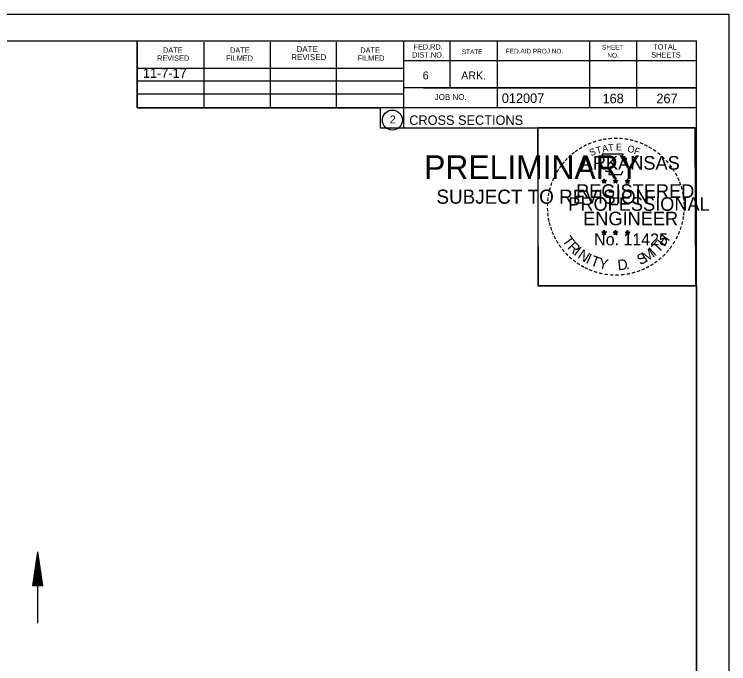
# Model space of a CAD drawing. Extents: x 1374311 to 1383814, y 384102 to 406278.
# Drawn here: x 1381686.5 to 1381791.6, y 388495.9 to 388591.4 of the extents above; entities that cross this region are included whole.
import ezdxf

# ---------------------------------------------------------------- set-up
doc = ezdxf.new("R2010")
doc.units = 0
for name, color, linetype in [('R_Border', 7, 'Continuous'), ('R_Border PE', 7, 'Continuous'), ('R_Border Prem', 7, 'Continuous'), ('R_Draft', 7, 'Continuous'), ('R_Fin Surface', 7, 'Continuous'), ('R_No Plot', 7, 'Continuous'), ('R_Water', 7, 'Continuous')]:
    doc.layers.add(name, color=color, linetype=linetype)

msp = doc.modelspace()

# ---------------------------------------------------------------- linework, layer by layer
at = {"layer": 'R_Border'}
for p, q in [((1381470.66, 388587.46), (1381786.84, 388587.46)), ((1381704.58, 388577.58), (1381704.58, 388587.46)), ((1381714.44, 388577.58), (1381714.44, 388587.26)), ((1381724.2, 388577.58), (1381724.2, 388587.26)), ((1381733.88, 388577.58), (1381733.88, 388587.26)), ((1381743.74, 388587.46), (1381743.74, 388574.66)), ((1381750.58, 388587.46), (1381750.58, 388580.52)), ((1381757.52, 388587.46), (1381757.52, 388577.58)), ((1381771.1, 388587.46), (1381771.1, 388577.58)), ((1381778.04, 388587.46), (1381778.04, 388577.58)), ((1381786.84, 388382), (1381786.84, 388587.46)), ((1381786.84, 388584.52), (1381743.74, 388584.52)), ((1381786.84, 388584.54), (1381786.84, 388584.54)), ((1381704.58, 388583.44), (1381743.74, 388583.44)), ((1381704.58, 388581.58), (1381743.74, 388581.58)), ((1381786.84, 388580.52), (1381743.74, 388580.52)), ((1381746.7, 388580.52), (1381786.84, 388580.52)), ((1381704.58, 388577.58), (1381704.58, 388579.64)), ((1381704.58, 388579.64), (1381743.74, 388579.64)), ((1381786.84, 388577.58), (1381704.58, 388577.58)), ((1381743.74, 388574.66), (1381786.84, 388574.66))]:
    msp.add_line(p, q, dxfattribs=at)
msp.add_circle((1381742.12, 388575.8), 1.47, dxfattribs=at)
at = {"layer": 'R_Border PE'}
for p, q in [((1381772.92, 388566.92), (1381773.27, 388566.81)), ((1381772.92, 388566.92), (1381773.18, 388566.87)), ((1381772.92, 388566.92), (1381773.16, 388566.8)), ((1381773.06, 388566.51), (1381773.27, 388566.81)), ((1381773.06, 388566.51), (1381773.18, 388566.76)), ((1381773.06, 388566.51), (1381773.27, 388566.73)), ((1381773.27, 388567.17), (1381773.23, 388566.92)), ((1381773.27, 388566.81), (1381773.27, 388567.17)), ((1381773.27, 388567.17), (1381773.32, 388566.92)), ((1381773.62, 388566.92), (1381773.27, 388566.81)), ((1381773.48, 388566.51), (1381773.27, 388566.81)), ((1381773.48, 388566.51), (1381773.27, 388566.73)), ((1381773.62, 388566.92), (1381773.33, 388566.87)), ((1381773.48, 388566.51), (1381773.35, 388566.8)), ((1381773.62, 388566.92), (1381773.41, 388566.82)), ((1381774.59, 388566.92), (1381774.94, 388566.81)), ((1381774.59, 388566.92), (1381774.85, 388566.87)), ((1381774.59, 388566.92), (1381774.83, 388566.8)), ((1381774.73, 388566.51), (1381774.94, 388566.81)), ((1381774.73, 388566.51), (1381774.85, 388566.76)), ((1381774.73, 388566.51), (1381774.94, 388566.73)), ((1381774.94, 388567.17), (1381774.9, 388566.92)), ((1381774.94, 388566.81), (1381774.94, 388567.17)), ((1381774.94, 388567.17), (1381774.99, 388566.92)), ((1381775.29, 388566.92), (1381774.94, 388566.81)), ((1381775.15, 388566.51), (1381774.94, 388566.81)), ((1381775.15, 388566.51), (1381774.94, 388566.73)), ((1381775.29, 388566.92), (1381775, 388566.87)), ((1381775.15, 388566.51), (1381775.02, 388566.8)), ((1381775.29, 388566.92), (1381775.08, 388566.82)), ((1381776.36, 388566.91), (1381776.71, 388566.8)), ((1381776.36, 388566.91), (1381776.61, 388566.86)), ((1381776.36, 388566.91), (1381776.59, 388566.79)), ((1381776.49, 388566.5), (1381776.71, 388566.8)), ((1381776.49, 388566.5), (1381776.62, 388566.74)), ((1381776.49, 388566.5), (1381776.7, 388566.72)), ((1381776.71, 388567.16), (1381776.66, 388566.91)), ((1381776.92, 388566.5), (1381776.7, 388566.71)), ((1381776.71, 388566.8), (1381776.71, 388567.16)), ((1381776.71, 388567.16), (1381776.75, 388566.91)), ((1381777.05, 388566.91), (1381776.71, 388566.8)), ((1381776.92, 388566.5), (1381776.71, 388566.8)), ((1381777.05, 388566.91), (1381776.77, 388566.86)), ((1381776.92, 388566.5), (1381776.78, 388566.79)), ((1381777.05, 388566.91), (1381776.85, 388566.81)), ((1381772.92, 388559.35), (1381773.27, 388559.24)), ((1381772.92, 388559.35), (1381773.17, 388559.3)), ((1381772.92, 388559.35), (1381773.16, 388559.22)), ((1381773.05, 388558.94), (1381773.27, 388559.24)), ((1381773.27, 388559.6), (1381773.23, 388559.35)), ((1381773.27, 388559.24), (1381773.27, 388559.6)), ((1381773.27, 388559.6), (1381773.32, 388559.35)), ((1381773.61, 388559.35), (1381773.27, 388559.24)), ((1381773.48, 388558.94), (1381773.27, 388559.24)), ((1381773.61, 388559.35), (1381773.33, 388559.3)), ((1381773.48, 388558.94), (1381773.34, 388559.23)), ((1381773.61, 388559.35), (1381773.41, 388559.24)), ((1381774.59, 388559.35), (1381774.94, 388559.24)), ((1381774.59, 388559.35), (1381774.84, 388559.3)), ((1381774.59, 388559.35), (1381774.82, 388559.22)), ((1381774.72, 388558.94), (1381774.94, 388559.24)), ((1381774.94, 388559.6), (1381774.9, 388559.35)), ((1381774.94, 388559.24), (1381774.94, 388559.6)), ((1381774.94, 388559.6), (1381774.99, 388559.35)), ((1381775.28, 388559.35), (1381774.94, 388559.24)), ((1381775.15, 388558.94), (1381774.94, 388559.24)), ((1381775.28, 388559.35), (1381775, 388559.3)), ((1381775.15, 388558.94), (1381775.01, 388559.23)), ((1381775.28, 388559.35), (1381775.08, 388559.24)), ((1381776.35, 388559.34), (1381776.7, 388559.23)), ((1381776.35, 388559.34), (1381776.61, 388559.29)), ((1381776.35, 388559.34), (1381776.59, 388559.21)), ((1381776.49, 388558.93), (1381776.7, 388559.23)), ((1381776.7, 388559.59), (1381776.66, 388559.34)), ((1381776.7, 388559.23), (1381776.7, 388559.59)), ((1381776.7, 388559.59), (1381776.75, 388559.34)), ((1381777.05, 388559.34), (1381776.7, 388559.23)), ((1381776.92, 388558.93), (1381776.7, 388559.23)), ((1381777.05, 388559.34), (1381776.76, 388559.29)), ((1381777.05, 388559.34), (1381776.85, 388559.23)), ((1381773.05, 388558.94), (1381773.18, 388559.18)), ((1381773.05, 388558.94), (1381773.27, 388559.16)), ((1381773.48, 388558.94), (1381773.27, 388559.15)), ((1381774.72, 388558.94), (1381774.85, 388559.18)), ((1381774.72, 388558.94), (1381774.93, 388559.16)), ((1381775.15, 388558.94), (1381774.93, 388559.15)), ((1381776.49, 388558.93), (1381776.61, 388559.17)), ((1381776.49, 388558.93), (1381776.7, 388559.15)), ((1381776.92, 388558.93), (1381776.7, 388559.14)), ((1381776.92, 388558.93), (1381776.78, 388559.22))]:
    msp.add_line(p, q, dxfattribs=at)
for points in [[(1381772.96, 388570.8), (1381773.23, 388569.97)], [(1381776.47, 388569.88), (1381776.62, 388570.16), (1381775.93, 388570.14), (1381776.08, 388570.8), (1381772.96, 388570.8)], [(1381773.46, 388568.37), (1381773.46, 388568.29), (1381774.02, 388568.27), (1381773.96, 388567.8), (1381775.83, 388567.8), (1381776.04, 388568.33)], [(1381773.27, 388567.17), (1381773.48, 388566.51), (1381772.92, 388566.92), (1381773.62, 388566.92), (1381773.06, 388566.51), (1381773.27, 388567.17)], [(1381774.94, 388567.17), (1381775.15, 388566.51), (1381774.59, 388566.92), (1381775.29, 388566.92), (1381774.73, 388566.51), (1381774.94, 388567.17)], [(1381776.71, 388567.16), (1381776.92, 388566.5), (1381776.36, 388566.91), (1381777.05, 388566.91), (1381776.49, 388566.5), (1381776.71, 388567.16)], [(1381773.27, 388559.6), (1381773.48, 388558.94), (1381772.92, 388559.35), (1381773.61, 388559.35), (1381773.05, 388558.94), (1381773.27, 388559.6)], [(1381774.94, 388559.6), (1381775.15, 388558.94), (1381774.59, 388559.35), (1381775.28, 388559.35), (1381774.72, 388558.94), (1381774.94, 388559.6)], [(1381776.7, 388559.59), (1381776.92, 388558.93), (1381776.35, 388559.34), (1381777.05, 388559.34), (1381776.49, 388558.93), (1381776.7, 388559.59)]]:
    msp.add_lwpolyline(points, dxfattribs=at)
for centre, radius in [((1381773.27, 388566.81), 0.172), ((1381773.27, 388566.81), 0.145), ((1381773.27, 388566.81), 0.116), ((1381773.27, 388566.81), 0.0991), ((1381773.27, 388566.81), 0.0747), ((1381773.27, 388566.81), 0.0495), ((1381773.27, 388566.81), 0.0296), ((1381774.94, 388566.81), 0.172), ((1381774.94, 388566.81), 0.145), ((1381774.94, 388566.81), 0.116), ((1381774.94, 388566.81), 0.0991), ((1381774.94, 388566.81), 0.0747), ((1381774.94, 388566.81), 0.0495), ((1381774.94, 388566.81), 0.0296), ((1381776.7, 388566.8), 0.172), ((1381776.7, 388566.8), 0.145), ((1381776.7, 388566.8), 0.116), ((1381776.7, 388566.8), 0.0991), ((1381776.7, 388566.8), 0.0747), ((1381776.7, 388566.8), 0.0495), ((1381776.7, 388566.8), 0.0296), ((1381773.27, 388559.23), 0.172), ((1381773.27, 388559.23), 0.145), ((1381773.27, 388559.23), 0.116), ((1381773.27, 388559.23), 0.0991), ((1381773.27, 388559.23), 0.0747), ((1381773.27, 388559.23), 0.0495), ((1381773.27, 388559.23), 0.0296), ((1381774.94, 388559.23), 0.172), ((1381774.94, 388559.23), 0.145), ((1381774.94, 388559.23), 0.116), ((1381774.94, 388559.23), 0.0991), ((1381774.94, 388559.23), 0.0747), ((1381774.94, 388559.23), 0.0495), ((1381774.94, 388559.23), 0.0296), ((1381776.7, 388559.22), 0.172), ((1381776.7, 388559.22), 0.145), ((1381776.7, 388559.22), 0.116), ((1381776.7, 388559.22), 0.0991), ((1381776.7, 388559.22), 0.0747), ((1381776.7, 388559.22), 0.0495), ((1381776.7, 388559.22), 0.0296)]:
    msp.add_circle(centre, radius, dxfattribs=at)
at = {"layer": 'R_Draft'}
for p, q in [((1381689.21, 388507.32), (1381689.96, 388512.32)), ((1381690.71, 388507.32), (1381689.96, 388512.32)), ((1381689.34, 388507.32), (1381689.96, 388511.49)), ((1381690.59, 388507.32), (1381689.96, 388511.49)), ((1381689.47, 388507.32), (1381689.96, 388510.63)), ((1381690.46, 388507.32), (1381689.96, 388510.63)), ((1381689.59, 388507.32), (1381689.96, 388509.79)), ((1381689.72, 388507.32), (1381689.96, 388508.95)), ((1381690.34, 388507.32), (1381689.96, 388509.79)), ((1381690.21, 388507.32), (1381689.96, 388508.95)), ((1381689.85, 388507.32), (1381689.96, 388508.11)), ((1381690.08, 388507.32), (1381689.96, 388508.11)), ((1381690.71, 388507.32), (1381689.21, 388507.32))]:
    msp.add_line(p, q, dxfattribs=at)
at = {"layer": 'R_No Plot'}
for p, q in [((1381458.26, 388591.36), (1381791.59, 388591.36)), ((1381762.87, 388552.21), (1381762.87, 388552.21))]:
    msp.add_line(p, q, dxfattribs=at)
for points in [[(1381458.25, 388591.36), (1381791.59, 388591.36), (1381791.59, 388378.02), (1381458.25, 388378.02)], [(1381704.58, 388587.46), (1381704.58, 388577.58), (1381740.31, 388577.58), (1381740.31, 388574.66), (1381763.51, 388574.66), (1381763.51, 388551.45), (1381786.84, 388551.45), (1381786.84, 388382), (1381470.66, 388382), (1381470.66, 388587.46)], [(1381763.51, 388574.7), (1381786.61, 388574.7), (1381786.72, 388551.45), (1381763.62, 388551.45)]]:
    msp.add_lwpolyline(points, close=True, dxfattribs=at)
at = {"layer": 'R_Water'}
msp.add_line((1381689.96, 388501.81), (1381689.96, 388512.32), dxfattribs=at)

# ---------------------------------------------------------------- texts
at = {"layer": 'R_Border'}
for s, height, p in [('DATE', 0.879, (1381728.02, 388585.8)), ('FED.RD.', 0.782, (1381745.22, 388586.18)), ('SHEET', 0.684, (1381772.96, 388586.18)), ('TOTAL', 0.782, (1381780.48, 388586.18)), ('DATE', 0.782, (1381708.38, 388585.7)), ('DATE', 0.782, (1381718.24, 388585.7)), ('REVISED', 0.879, (1381727.24, 388584.62)), ('DATE', 0.782, (1381737.4, 388585.7)), ('DIST.NO.', 0.782, (1381745.02, 388585)), ('STATE', 0.684, (1381752.34, 388585.5)), ('FED.AID PROJ.NO.', 0.684, (1381758.8, 388585.6)), ('NO.', 0.684, (1381773.74, 388585)), ('SHEETS', 0.782, (1381780.2, 388585)), ('REVISED', 0.782, (1381707.5, 388584.52)), ('FILMED', 0.782, (1381717.66, 388584.52)), ('FILMED', 0.782, (1381737, 388584.52)), ('6', 1.17, (1381746.58, 388581.78)), ('ARK.', 1.172, (1381752.24, 388581.78)), ('JOB NO.', 0.879, (1381748.34, 388578.76)), ('012007', 1.4, (1381758.21, 388578.32)), ('2', 1.17, (1381741.74, 388575.31)), ('CROSS SECTIONS', 1.4, (1381744.6, 388575.09))]:
    msp.add_text(s, height=height, rotation=360, dxfattribs=at).set_placement(p)
at = {"layer": 'R_Border PE'}
for s, height, rotation, p in [('-', 1.6, 13.6301, (1381772.46, 388572.17)), ('-', 1.6, 10.2193, (1381773.14, 388572.33)), ('-', 1.6, 5.8968, (1381773.87, 388572.44)), ('-', 1.6, 0.1862, (1381774.64, 388572.51)), ('-', 1.6, 357.743, (1381775.36, 388572.5)), ('-', 1.6, 352.1617, (1381776.11, 388572.44)), ('-', 1.6, 347.2049, (1381776.83, 388572.33)), ('-', 1.6, 34.0636, (1381769.85, 388570.97)), ('-', 1.6, 28.7918, (1381770.44, 388571.34)), ('-', 1.6, 24.3072, (1381771.08, 388571.66)), ('-', 1.6, 19.1761, (1381771.71, 388571.92)), ('T', 1, 16.4036, (1381772.23, 388570.81)), ('A', 1, 11.2132, (1381773.06, 388571.06)), ('T', 1, 6.0228, (1381773.91, 388571.22)), ('E', 1, 0.8323, (1381775.01, 388571.33)), ('O', 1, 350.4515, (1381776.62, 388571.12)), ('-', 1.6, 342.3362, (1381777.46, 388572.17)), ('-', 1.6, 337.8551, (1381778.2, 388571.95)), ('-', 1.6, 334.1211, (1381778.83, 388571.68)), ('-', 1.6, 329.6409, (1381779.41, 388571.39)), ('-', 1.6, 38.9507, (1381768.79, 388570.2)), ('-', 1.6, 36.2317, (1381769.27, 388570.57)), ('S', 1, 21.594, (1381771.32, 388570.48)), ('F', 1, 340.0707, (1381777.57, 388570.9)), ('-', 1.6, 325.8627, (1381780.05, 388571.03)), ('-', 1.6, 320.5297, (1381780.66, 388570.61)), ('-', 1.6, 50.6142, (1381767.51, 388568.81)), ('-', 1.6, 48.423, (1381767.91, 388569.3)), ('-', 1.6, 42.9622, (1381768.36, 388569.78)), ('ARKANSAS', 2, 360, (1381769.82, 388568.51)), ('-', 1.6, 315.5786, (1381781.26, 388570.12)), ('-', 1.6, 309.8797, (1381781.83, 388569.57)), ('-', 1.6, 54.2325, (1381767.1, 388568.25)), ('-', 1.6, 306.6522, (1381782.35, 388568.97)), ('-', 1.6, 62.8713, (1381766.46, 388567.11)), ('-', 1.6, 58.0706, (1381766.77, 388567.72)), ('-', 1.4, 303.6753, (1381782.84, 388568.4)), ('-', 1.6, 299.6684, (1381783.16, 388567.79)), ('-', 1.6, 72.3945, (1381765.98, 388565.87)), ('-', 1.6, 67.7743, (1381766.2, 388566.5)), ('DWB', 0.01, 360, (1381773.26, 388566.8)), ('DWB', 0.01, 360, (1381774.93, 388566.8)), ('DWB', 0.01, 360, (1381776.69, 388566.79)), ('-', 1.6, 294.6628, (1381783.48, 388567.18)), ('-', 1.6, 290.5728, (1381783.74, 388566.6)), ('-', 1.6, 75.461, (1381765.78, 388565.15)), ('REGISTERED', 2, 360, (1381769.14, 388564.36)), ('-', 1.6, 285.1233, (1381783.97, 388566.02)), ('-', 1.6, 81.2013, (1381765.65, 388564.44)), ('PROFESSIONAL', 2, 360, (1381767.99, 388562.46)), ('-', 1.6, 280.5493, (1381784.17, 388565.28)), ('-', 1.6, 276.5962, (1381784.33, 388564.51)), ('-', 1.6, 89.0622, (1381765.55, 388563.05)), ('-', 1.6, 85.1863, (1381765.57, 388563.75)), ('-', 1.6, 274.3301, (1381784.39, 388563.79)), ('-', 1.6, 94.1959, (1381765.58, 388562.32)), ('-', 1.6, 269.9407, (1381784.43, 388563.16)), ('-', 1.6, 98.9479, (1381765.66, 388561.65)), ('-', 1.6, 101.7149, (1381765.79, 388560.92)), ('ENGINEER', 2, 360, (1381770.18, 388560.33)), ('-', 1.6, 260.9953, (1381784.34, 388561.84)), ('-', 1.6, 263.5172, (1381784.41, 388562.49)), ('-', 1.6, 105.4578, (1381765.95, 388560.33)), ('-', 1.6, 255.7626, (1381784.23, 388561.16)), ('-', 1.6, 109.0874, (1381766.17, 388559.7)), ('-', 1.6, 114.0643, (1381766.42, 388559.1)), ('DWB', 0.01, 360, (1381773.25, 388559.23)), ('DWB', 0.01, 360, (1381774.92, 388559.23)), ('DWB', 0.01, 360, (1381776.69, 388559.22)), ('-', 1.6, 247.8887, (1381783.82, 388559.77)), ('-', 1.6, 252.8681, (1381784.05, 388560.44)), ('-', 1.6, 115.7289, (1381766.73, 388558.48)), ('T', 1.54, 306.0406, (1381767.03, 388558.07)), ('No. 11425', 1.757, 360, (1381771.8, 388557.38)), ('H', 1.54, 54.6088, (1381782.15, 388557.11)), ('-', 1.6, 244.6197, (1381783.56, 388559.14)), ('-', 1.6, 120.4471, (1381767.08, 388557.9)), ('-', 1.6, 125.8934, (1381767.49, 388557.33)), ('R', 1.54, 314.005, (1381767.79, 388557.03)), ('I', 1.54, 321.9694, (1381768.69, 388556.09)), ('T', 1.54, 46.6444, (1381781.26, 388556.17)), ('-', 1.6, 233.8452, (1381782.77, 388557.73)), ('-', 1.6, 239.0712, (1381783.17, 388558.39)), ('-', 1.6, 130.7181, (1381767.95, 388556.78)), ('-', 1.6, 134.2238, (1381768.47, 388556.24)), ('N', 1.54, 326.5002, (1381769.26, 388555.62)), ('I', 1.54, 335.3603, (1381770.47, 388554.84)), ('S', 1.54, 26.9312, (1381778.57, 388554.44)), ('M', 1.54, 32.6563, (1381779.41, 388554.84)), ('I', 1.54, 42.1136, (1381780.7, 388555.69)), ('-', 1.6, 225.7653, (1381781.86, 388556.6)), ('-', 1.6, 231.2538, (1381782.34, 388557.17)), ('-', 1.6, 138.9338, (1381768.99, 388555.77)), ('-', 1.6, 144.6463, (1381769.55, 388555.37)), ('T', 1.54, 339.8912, (1381771.13, 388554.51)), ('Y', 1.54, 347.8556, (1381772.34, 388554.06)), ('D', 1.54, 6.3969, (1381775.33, 388553.7)), ('-', 1.6, 215.7363, (1381780.79, 388555.62)), ('-', 1.6, 221.0851, (1381781.33, 388556.1)), ('-', 1.6, 148.0898, (1381770.11, 388555)), ('-', 1.6, 151.5704, (1381770.69, 388554.67)), ('-', 1.6, 154.6002, (1381771.21, 388554.42)), ('.', 1.54, 13.7642, (1381776.52, 388553.83)), ('-', 1.6, 204.2516, (1381779.07, 388554.57)), ('-', 1.6, 207.3568, (1381779.69, 388554.89)), ('-', 1.6, 212.2491, (1381780.25, 388555.24)), ('-', 1.6, 158.5612, (1381771.83, 388554.17)), ('-', 1.6, 162.7983, (1381772.52, 388553.96)), ('-', 1.6, 167.5555, (1381773.24, 388553.79)), ('-', 1.6, 173.1155, (1381774.01, 388553.68)), ('-', 1.6, 176.5183, (1381774.76, 388553.63)), ('-', 1.6, 181.5918, (1381775.5, 388553.65)), ('-', 1.6, 185.8167, (1381776.31, 388553.73)), ('-', 1.6, 191.2858, (1381777.04, 388553.86)), ('-', 1.6, 195.4743, (1381777.77, 388554.06)), ('-', 1.6, 200.7184, (1381778.45, 388554.3))]:
    msp.add_text(s, height=height, rotation=rotation, dxfattribs=at).set_placement(p)
at = {"layer": 'R_Border Prem'}
for s, height, p in [('PRELIMINARY', 3.5, (1381746.79, 388567.13)), ('DWB', 0.01, (1381747.53, 388568.98)), ('SUBJECT TO REVISION', 2.0751, (1381748.6, 388563.5))]:
    msp.add_text(s, height=height, rotation=360, dxfattribs=at).set_placement(p)
at = {"layer": 'R_Fin Surface'}
msp.add_text('11-7-17', height=1.4, dxfattribs=at).set_placement((1381705.42, 388582.01))
at = {"layer": 'R_Water'}
for s, p in [('168', (1381773.03, 388578.28)), ('267', (1381780.95, 388578.28))]:
    msp.add_text(s, height=1.4, rotation=360, dxfattribs=at).set_placement(p)

doc.saveas('drawing.dxf')
